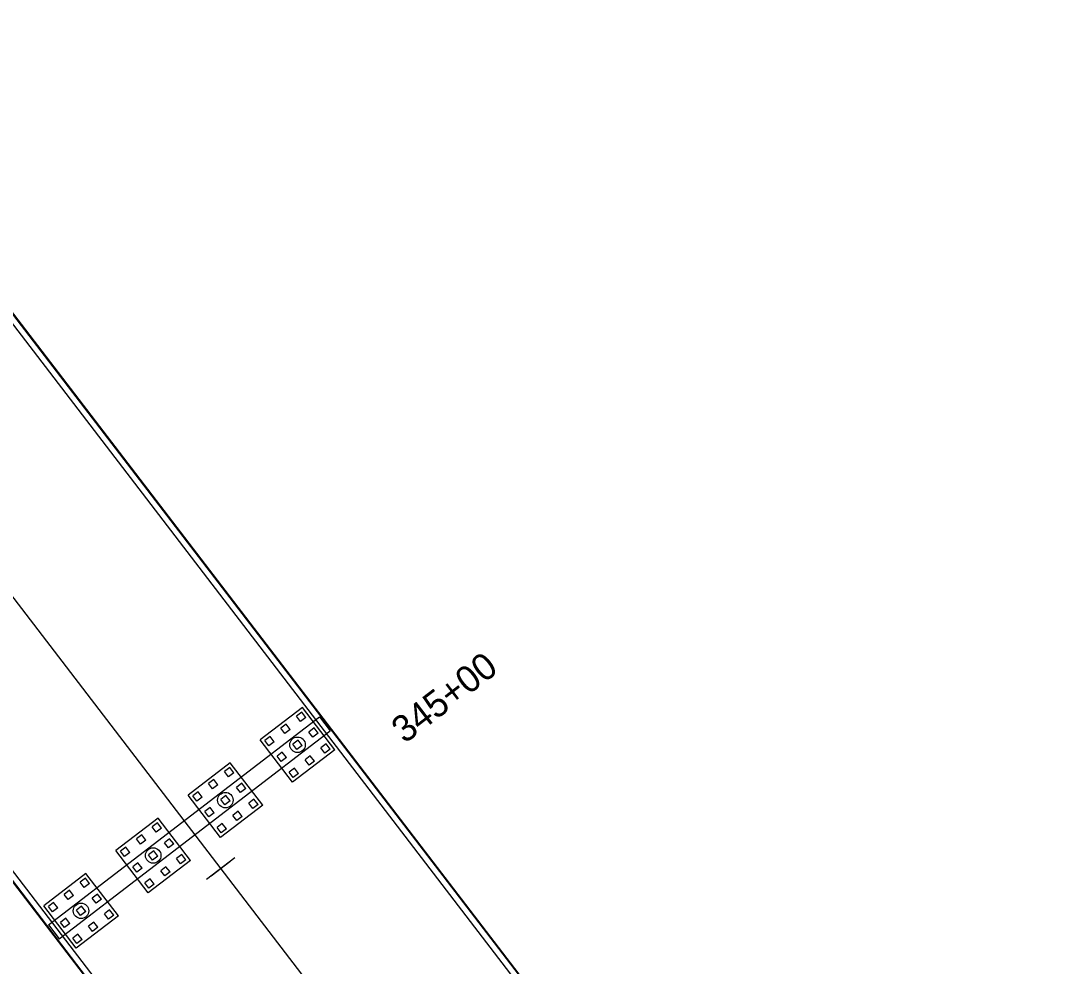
# Model space of a CAD drawing. Extents: x 881426 to 887360, y 1564404 to 1567430.
# Drawn here: x 883927.2 to 884159.8, y 1565646.2 to 1565859.3 of the extents above; entities that cross this region are included whole.
import ezdxf

# ---------------------------------------------------------------- set-up
doc = ezdxf.new("R2010")
doc.units = 0
for name, color, linetype in [('B_Concrete', 7, 'Continuous'), ('B_Concrete hidden', 7, 'Continuous'), ('R_Horz Alg', 7, 'Continuous'), ('R_Horz Alg Annot', 7, 'Continuous')]:
    doc.layers.add(name, color=color, linetype=linetype)

msp = doc.modelspace()

# ---------------------------------------------------------------- linework, layer by layer
at = {"layer": 'B_Concrete'}
for p, q in [((884070.92, 1565601.14), (883842.93, 1565898.55)), ((884071.97, 1565601.95), (883843.99, 1565899.36)), ((884071.97, 1565601.95), (883843.99, 1565899.36)), ((884072.11, 1565602.05), (883844.12, 1565899.47)), ((884010.2, 1565554.6), (883782.22, 1565852.01)), ((884010.33, 1565554.7), (883782.35, 1565852.11)), ((884010.33, 1565554.7), (883782.35, 1565852.11)), ((884011.39, 1565555.51), (883783.41, 1565852.92))]:
    msp.add_line(p, q, dxfattribs=at)
at = {"layer": 'B_Concrete hidden'}
for p, q in [((883990.72, 1565704.52), (883981.2, 1565697.22)), ((883990.59, 1565703.47), (883989.39, 1565702.56)), ((883991.5, 1565702.28), (883990.59, 1565703.47)), ((883998.02, 1565695), (883990.72, 1565704.52)), ((883933.44, 1565655.57), (883994.55, 1565702.41)), ((883987.01, 1565700.73), (883985.82, 1565699.82)), ((883987.93, 1565699.54), (883987.01, 1565700.73)), ((883990.31, 1565701.37), (883989.39, 1565702.56)), ((883991.5, 1565702.28), (883990.31, 1565701.37)), ((883994.55, 1565702.41), (883996.98, 1565699.24)), ((883935.87, 1565652.39), (883996.98, 1565699.24)), ((883986.74, 1565698.63), (883985.82, 1565699.82)), ((883987.93, 1565699.54), (883986.74, 1565698.63)), ((883993.32, 1565699.9), (883992.13, 1565698.98)), ((883993.05, 1565697.79), (883992.13, 1565698.98)), ((883994.24, 1565698.71), (883993.05, 1565697.79)), ((883994.24, 1565698.71), (883993.32, 1565699.9)), ((883988.5, 1565687.7), (883981.2, 1565697.22)), ((883983.44, 1565697.99), (883982.25, 1565697.08)), ((883983.16, 1565695.89), (883982.25, 1565697.08)), ((883984.35, 1565696.8), (883983.16, 1565695.89)), ((883984.35, 1565696.8), (883983.44, 1565697.99)), ((883989.75, 1565697.16), (883988.56, 1565696.25)), ((883989.47, 1565695.06), (883988.56, 1565696.25)), ((883990.66, 1565695.97), (883989.47, 1565695.06)), ((883990.66, 1565695.97), (883989.75, 1565697.16)), ((883996.06, 1565696.33), (883994.87, 1565695.41)), ((883996.97, 1565695.14), (883996.06, 1565696.33)), ((883986.18, 1565694.42), (883984.99, 1565693.51)), ((883987.09, 1565693.23), (883986.18, 1565694.42)), ((883998.02, 1565695), (883988.5, 1565687.7)), ((883995.78, 1565694.22), (883994.87, 1565695.41)), ((883996.97, 1565695.14), (883995.78, 1565694.22)), ((883974.45, 1565692.05), (883964.93, 1565684.75)), ((883981.75, 1565682.52), (883974.45, 1565692.05)), ((883985.9, 1565692.32), (883984.99, 1565693.51)), ((883987.09, 1565693.23), (883985.9, 1565692.32)), ((883992.49, 1565693.59), (883991.3, 1565692.68)), ((883992.21, 1565691.49), (883991.3, 1565692.68)), ((883993.4, 1565692.4), (883992.21, 1565691.49)), ((883993.4, 1565692.4), (883992.49, 1565693.59)), ((883974.32, 1565691), (883973.12, 1565690.08)), ((883974.04, 1565688.89), (883973.12, 1565690.08)), ((883975.23, 1565689.81), (883974.04, 1565688.89)), ((883975.23, 1565689.81), (883974.32, 1565691)), ((883988.92, 1565690.85), (883987.73, 1565689.94)), ((883988.64, 1565688.75), (883987.73, 1565689.94)), ((883989.83, 1565689.66), (883988.64, 1565688.75)), ((883989.83, 1565689.66), (883988.92, 1565690.85)), ((883970.74, 1565688.26), (883969.55, 1565687.35)), ((883970.47, 1565686.16), (883969.55, 1565687.35)), ((883971.66, 1565687.07), (883970.47, 1565686.16)), ((883971.66, 1565687.07), (883970.74, 1565688.26)), ((883977.05, 1565687.43), (883975.86, 1565686.51)), ((883977.97, 1565686.24), (883977.05, 1565687.43)), ((883972.23, 1565675.22), (883964.93, 1565684.75)), ((883967.17, 1565685.52), (883965.98, 1565684.61)), ((883966.89, 1565683.42), (883965.98, 1565684.61)), ((883968.09, 1565684.33), (883966.89, 1565683.42)), ((883968.09, 1565684.33), (883967.17, 1565685.52)), ((883973.48, 1565684.69), (883972.29, 1565683.78)), ((883974.39, 1565683.5), (883973.48, 1565684.69)), ((883976.78, 1565685.32), (883975.86, 1565686.51)), ((883977.97, 1565686.24), (883976.78, 1565685.32)), ((883981.75, 1565682.52), (883972.23, 1565675.22)), ((883973.2, 1565682.58), (883972.29, 1565683.78)), ((883974.39, 1565683.5), (883973.2, 1565682.58)), ((883979.79, 1565683.85), (883978.6, 1565682.94)), ((883979.51, 1565681.75), (883978.6, 1565682.94)), ((883980.7, 1565682.66), (883979.51, 1565681.75)), ((883980.7, 1565682.66), (883979.79, 1565683.85)), ((883969.91, 1565681.95), (883968.72, 1565681.04)), ((883969.63, 1565679.85), (883968.72, 1565681.04)), ((883970.82, 1565680.76), (883969.63, 1565679.85)), ((883970.82, 1565680.76), (883969.91, 1565681.95)), ((883976.22, 1565681.12), (883975.03, 1565680.2)), ((883975.94, 1565679.01), (883975.03, 1565680.2)), ((883977.13, 1565679.93), (883975.94, 1565679.01)), ((883977.13, 1565679.93), (883976.22, 1565681.12)), ((883958.18, 1565679.58), (883948.66, 1565672.28)), ((883958.05, 1565678.53), (883956.86, 1565677.61)), ((883957.77, 1565676.42), (883956.86, 1565677.61)), ((883958.96, 1565677.33), (883957.77, 1565676.42)), ((883958.96, 1565677.33), (883958.05, 1565678.53)), ((883965.49, 1565670.05), (883958.18, 1565679.58)), ((883972.65, 1565678.38), (883971.46, 1565677.47)), ((883972.37, 1565676.28), (883971.46, 1565677.47)), ((883973.56, 1565677.19), (883972.65, 1565678.38)), ((883954.47, 1565675.79), (883953.28, 1565674.88)), ((883955.39, 1565674.6), (883954.47, 1565675.79)), ((883973.56, 1565677.19), (883972.37, 1565676.28)), ((883950.9, 1565673.05), (883949.71, 1565672.14)), ((883951.82, 1565671.86), (883950.9, 1565673.05)), ((883954.2, 1565673.68), (883953.28, 1565674.88)), ((883955.39, 1565674.6), (883954.2, 1565673.68)), ((883960.78, 1565674.95), (883959.59, 1565674.04)), ((883960.51, 1565672.85), (883959.59, 1565674.04)), ((883961.7, 1565673.76), (883960.51, 1565672.85)), ((883961.7, 1565673.76), (883960.78, 1565674.95)), ((883955.96, 1565662.75), (883948.66, 1565672.28)), ((883950.62, 1565670.95), (883949.71, 1565672.14)), ((883951.82, 1565671.86), (883950.62, 1565670.95)), ((883957.21, 1565672.22), (883956.02, 1565671.3)), ((883956.93, 1565670.11), (883956.02, 1565671.3)), ((883958.12, 1565671.03), (883956.93, 1565670.11)), ((883958.12, 1565671.03), (883957.21, 1565672.22)), ((883963.52, 1565671.38), (883962.33, 1565670.47)), ((883963.24, 1565669.28), (883962.33, 1565670.47)), ((883964.43, 1565670.19), (883963.52, 1565671.38)), ((883953.64, 1565669.48), (883952.45, 1565668.57)), ((883953.36, 1565667.38), (883952.45, 1565668.57)), ((883954.55, 1565668.29), (883953.36, 1565667.38)), ((883954.55, 1565668.29), (883953.64, 1565669.48)), ((883965.49, 1565670.05), (883955.96, 1565662.75)), ((883959.95, 1565668.64), (883958.76, 1565667.73)), ((883960.86, 1565667.45), (883959.95, 1565668.64)), ((883964.43, 1565670.19), (883963.24, 1565669.28)), ((883941.91, 1565667.11), (883932.39, 1565659.8)), ((883941.78, 1565666.05), (883940.59, 1565665.14)), ((883942.69, 1565664.86), (883941.78, 1565666.05)), ((883949.22, 1565657.58), (883941.91, 1565667.11)), ((883956.38, 1565665.91), (883955.19, 1565664.99)), ((883957.29, 1565664.72), (883956.38, 1565665.91)), ((883959.67, 1565666.54), (883958.76, 1565667.73)), ((883960.86, 1565667.45), (883959.67, 1565666.54)), ((883941.5, 1565663.95), (883940.59, 1565665.14)), ((883942.69, 1565664.86), (883941.5, 1565663.95)), ((883956.1, 1565663.8), (883955.19, 1565664.99)), ((883957.29, 1565664.72), (883956.1, 1565663.8)), ((883938.2, 1565663.32), (883937.01, 1565662.4)), ((883937.93, 1565661.21), (883937.01, 1565662.4)), ((883939.12, 1565662.13), (883937.93, 1565661.21)), ((883939.12, 1565662.13), (883938.2, 1565663.32)), ((883944.51, 1565662.48), (883943.32, 1565661.57)), ((883944.24, 1565660.38), (883943.32, 1565661.57)), ((883945.43, 1565661.29), (883944.24, 1565660.38)), ((883945.43, 1565661.29), (883944.51, 1565662.48)), ((883939.69, 1565650.28), (883932.39, 1565659.8)), ((883934.63, 1565660.58), (883933.44, 1565659.67)), ((883934.36, 1565658.48), (883933.44, 1565659.67)), ((883935.55, 1565659.39), (883934.36, 1565658.48)), ((883935.55, 1565659.39), (883934.63, 1565660.58)), ((883940.94, 1565659.74), (883939.75, 1565658.83)), ((883940.66, 1565657.64), (883939.75, 1565658.83)), ((883941.85, 1565658.55), (883940.94, 1565659.74)), ((883947.25, 1565658.91), (883946.06, 1565658)), ((883948.16, 1565657.72), (883947.25, 1565658.91)), ((883937.37, 1565657.01), (883936.18, 1565656.09)), ((883938.28, 1565655.82), (883937.37, 1565657.01)), ((883949.22, 1565657.58), (883939.69, 1565650.28)), ((883941.85, 1565658.55), (883940.66, 1565657.64)), ((883946.97, 1565656.81), (883946.06, 1565658)), ((883948.16, 1565657.72), (883946.97, 1565656.81)), ((883933.44, 1565655.57), (883935.87, 1565652.39)), ((883937.09, 1565654.9), (883936.18, 1565656.09)), ((883938.28, 1565655.82), (883937.09, 1565654.9)), ((883943.68, 1565656.17), (883942.49, 1565655.26)), ((883943.4, 1565654.07), (883942.49, 1565655.26)), ((883944.59, 1565654.98), (883943.4, 1565654.07)), ((883944.59, 1565654.98), (883943.68, 1565656.17)), ((883940.11, 1565653.44), (883938.92, 1565652.52)), ((883939.83, 1565651.33), (883938.92, 1565652.52)), ((883941.02, 1565652.24), (883939.83, 1565651.33)), ((883941.02, 1565652.24), (883940.11, 1565653.44))]:
    msp.add_line(p, q, dxfattribs=at)
for centre in [(883989.61, 1565696.11), (883973.34, 1565683.64), (883957.07, 1565671.16), (883940.8, 1565658.69)]:
    msp.add_circle(centre, 1.75, dxfattribs=at)
at = {"layer": 'R_Horz Alg'}
msp.add_line((883399.11, 1566415.89), (884332.67, 1565198.04), dxfattribs=at)
at = {"layer": 'R_Horz Alg Annot'}
msp.add_line((883970.15, 1565666.57), (883974.38, 1565669.81), dxfattribs=at)
msp.add_lwpolyline([(883975.44, 1565670.63), (883969.09, 1565665.76)], dxfattribs=at)

# ---------------------------------------------------------------- texts
msp.add_text('345+00', height=6, rotation=37.4722, dxfattribs=at).set_placement((884013.77, 1565696.23))

doc.saveas('drawing.dxf')
